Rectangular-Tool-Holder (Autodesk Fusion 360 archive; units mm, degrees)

design "Rectangular-Tool-Holder" references "Base"
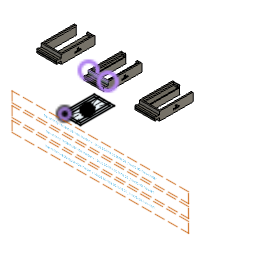
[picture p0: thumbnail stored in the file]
parameter "tool_width" = 36.5
parameter "tool_length" = 69
parameter "tool_slot_height" = 5
parameter "holder_hole_width" = 25
parameter "wall_thickness" = 5
sketch "Base" plane through (0, 0, 0) normal (0, 0, 1) x axis (1, 0, 0)
  line L1 (36.5, 0) -> (0, 0)
  line L2 (36.5, 69) -> (36.5, 0)
  line L3 (0, 69) -> (36.5, 69)
  line L4 (0, 0) -> (0, 69)
  line L5 (41.5, -5) -> (-5, -5)
  line L6 (41.5, 74) -> (41.5, -5)
  line L7 (-5, 74) -> (41.5, 74)
  line L8 (-5, -5) -> (-5, 74)
  line L9 (18.25, -5) -> (18.25, 74)
  line L10 (5.75, 74) -> (30.75, 74)
  line L11 (5.75, -5) -> (5.75, 74)
  line L12 (30.75, -5) -> (5.75, -5)
  line L13 (30.75, 74) -> (30.75, -5)
  line L14 (5.75, -5) -> (30.75, 74)
  line L15 (30.75, -5) -> (5.75, 74)
  point P1 (0, 0)
  point P2 (0, 0)
  point P10 (18.25, 74)
  point P11 (18.25, -5)
  point P16 (18.25, 34.5)
  point P3 (36.5, 0)
  point P5 (0, 69)
  point P14 (5.75, -5)
  point P15 (30.75, -5)
  point P13 (5.75, 74)
  horizontal L1
  vertical L2
  horizontal L3
  vertical L4
  coincident P1 P2
  midpoint L7 P10
  midpoint L5 P11
  horizontal L10
  perpendicular L10 L11
  parallel L10 L12
  parallel L11 L13
  coincident L14 P16
  coincident L15 P16
  midpoint L9 P16
  dimension "d7" distance P2 P3 = 36.5 (= "tool_width")
  dimension "d8" distance P2 P5 = 69 (= "tool_length")
  dimension "d9" = 5 (= "wall_thickness")
  dimension "d10" distance P14 P15 = 25 (= "holder_hole_width")
  dimension "d11" distance P13 P14 = 79 (= "tool_length + wall_thickness + wall_thickness")
extrude "Extrude1" new body sketch "Base" profile of L1 L2 L3 L4 L8 L7 L6 L5 L11 L13 against normal blind 5 (magnitude of "wall_thickness * -1")
extrude "Extrude2" add sketch "Base" profile of L1 L2 L3 L4 L8 L7 L6 L5 L11 L13 along normal blind 5 (= "tool_slot_height")
component_insert "Component Insert"
sketch "Reference" plane through (0, 55.6118, 0) normal (0, 1, 0) x axis (-1, 0, 0)
  line L1 (0, 52.6059) -> (-45, 52.6059)
  line L2 (0, 60) -> (0, 52.6059)
  line L3 (-45, 60) -> (0, 60)
  line L4 (-45, 52.6059) -> (-45, 60)
  line L5 (-45, 60) -> (0, 60)
move "Move1"
move "Move2"
extrude "Extrude3" new body of existing geometry blind 10
extrude "Extrude4" add of existing geometry to an object
extrude "Extrude5" cut of existing geometry to an object
extrude "Extrude6" add of existing geometry blind 10
sketch "Text 1" plane through (45.75, 0, 0) normal (1, 0, 0) x axis (0, 1, 0)
  line L1 (48.9918, 52.4859) -> (55.6118, 52.4859)
  line L2 (48.9918, 53.9359) -> (48.9918, 52.4859)
  line L3 (44.7318, 53.9359) -> (48.9918, 53.9359)
  line L4 (44.7318, 50.6559) -> (44.7318, 53.9359)
  line L5 (44.7318, 45.6759) -> (44.7318, 48.9559)
  line L6 (48.9918, 45.6759) -> (44.7318, 45.6759)
  line L7 (48.9918, 47.1259) -> (48.9918, 45.6759)
  line L8 (55.6118, 47.1259) -> (48.9918, 47.1259)
  curve K1
  curve K2
  curve K3
  curve K4
  line L9 (134.6118, 60) -> (55.6118, 60)
  line L10 (134.6118, 60) -> (134.6118, 40)
  line L11 (134.6118, 60) -> (134.6118, 40)
  line L12 (55.6118, 60) -> (134.6118, 60)
  line L13 (134.6118, 40) -> (55.6118, 40)
  line L14 (55.6118, 52.4859) -> (55.6118, 60)
  line L15 (55.6118, 40) -> (55.6118, 47.1259)
  arc A1 centre (44.7318, 49.8059) radius 0.85 clockwise from (44.7318, 50.6559) to (44.7318, 48.9559)
  parallel K3 L9
  equal K3 L9
  equal K2 L10
  midpoint L10
  dimension "d26" Text1-Height = 3
sketch "Text 2" plane through (-0.75, 0, 0) normal (-1, 0, 0) x axis (0, -1, 0)
  curve K1
  curve K2
  curve K3
  curve K4
  line L1 (-134.6118, 60) -> (-55.6118, 60)
  line L2 (-55.6118, 40) -> (-134.6118, 40)
  line L3 (-134.6118, 40) -> (-134.6118, 60)
  line L4 (-48.9918, 47.1259) -> (-55.6118, 47.1259)
  line L5 (-48.9918, 45.6759) -> (-48.9918, 47.1259)
  line L6 (-44.7318, 45.6759) -> (-48.9918, 45.6759)
  line L7 (-44.7318, 48.9559) -> (-44.7318, 45.6759)
  line L8 (-44.7318, 53.9359) -> (-44.7318, 50.6559)
  line L9 (-48.9918, 53.9359) -> (-44.7318, 53.9359)
  line L10 (-48.9918, 52.4859) -> (-48.9918, 53.9359)
  line L11 (-55.6118, 52.4859) -> (-48.9918, 52.4859)
  line L12 (-55.6118, 60) -> (-55.6118, 52.4859)
  line L13 (-55.6118, 47.1259) -> (-55.6118, 40)
  arc A1 centre (-44.7318, 49.8059) radius 0.85 clockwise from (-44.7318, 48.9559) to (-44.7318, 50.6559)
  point P3 (-134.6118, 60)
  point P2 (-55.6118, 40)
  equal K3 L1
  parallel K3 L1
  coincident P3
  coincident P2
  dimension "d27" Text1-Height = 3
extrude "Extrude7" cut sketch "Text 2" + "Text 1" distance -2
sketch "Filename" plane through (0, 0, 0) normal (0, 1, 0) x axis (1, 0, 0)
  dimension "d30" = 5
  dimension "d50" = 5
  dimension "d51" = 5
extrude "Extrude8" add of existing geometry to an object
extrude "Extrude9" cut of existing geometry to an object
copy_paste_bodies "CopyPasteBodies1"
move "Move3"
extrude "Extrude10" cut of existing geometry to an object
copy_paste_bodies "CopyPasteBodies2"
move "Move4"
extrude "Extrude11" cut of existing geometry to an object
extrude "Extrude12" cut of existing geometry to an object
extrude "Extrude13" add of existing geometry blind 5.5 (= "( ( 29 - 18 ) / 2 ) * 1 mm")
extrude "Extrude14" cut of existing geometry to an object
extrude "Extrude15" add of existing geometry blind 5.5 (= "( ( 29 - 18 ) / 2 ) * 1 mm")
fillet "Fillet1" radius 2
fillet "Fillet2" radius 1
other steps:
base_feature "Base Feature1" bodies "Right"
base_feature "Base Feature2" bodies "Center", "Left"
named bodies: "Center", "Right", "Left"

design "Base"
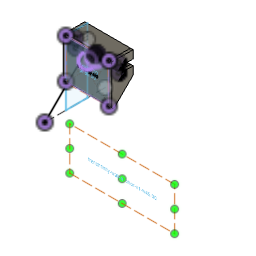
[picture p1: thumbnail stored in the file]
parameter "wall_anchor_height" = 60
parameter "wall_anchor_width" = 20
parameter "wall_anchor_angle" = 45
parameter "width_per_slot" = 40
parameter "slot_inner_width" = 8.5
parameter "slot_inner_height" = 4.5
parameter "slot_outer_width" = 5.6
parameter "slot_outer_height" = 6.5
parameter "slot_dept" = 15
parameter "print_tolerance" = 0.12
parameter "base_plate_thickness" = 16
parameter "base_plate_slot_height" = 50
parameter "wall_anchor_angle_rounded_border" = 1.5
parameter "base_plate_screw_hole_diameter" = 4
parameter "base_plate_screw_head_diameter" = 8
parameter "base_plate_screw_head_height" = 4
parameter "base_plate_screw_hole_side_distance" = 7
parameter "slot_screw_head_width" = 4.42 (= "4.3 mm + print_tolerance")
parameter "slot_screw_thread_width" = 2.12 (= "2 mm + print_tolerance")
parameter "slot_screw_head_height" = 2.12 (= "2 mm + print_tolerance")
parameter "width" = 45
parameter "filament_hole_width" = 1.7
parameter "plate_height" = 80
sketch "Side" plane through (0, 0, 0) normal (1, 0, 0) x axis (0, 1, 0)
  line L1 (39.6118, 0) -> (19.6118, 0)
  line L2 (39.6118, 60) -> (39.6118, 0)
  line L3 (19.6118, 60) -> (39.6118, 60)
  line L4 (19.6118, 0) -> (19.6118, 60)
  line L5 (39.6118, 39.6118) -> (0, 0)
  line L6 (56.0196, 0) -> (0, 0)
  point P1 (0, 0)
  point P6 (0, 0)
  point P7 (39.6118, 39.6118)
  point P2 (19.6118, 0)
  point P3 (39.6118, 0)
  point P5 (19.6118, 60)
  horizontal L1
  vertical L2
  horizontal L3
  vertical L4
  horizontal L6
  coincident P1 P6
  coincident L2 P7
  dimension "d4" distance P2 P3 = 20 (= "wall_anchor_width")
  dimension "d5" distance P2 P5 = 60 (= "wall_anchor_height")
  dimension "d6" angle L5 L6 = 45 (= "wall_anchor_angle")
extrude "Extrude1" new body sketch "Side" profile of L1 L2 L3 L4 L5 along normal blind 40 (= "width_per_slot")
sketch "Slot LeftToRight" plane through (0, 0, 0) normal (-1, 0, 0) x axis (0, -1, 0)
  line L1 (-19.6118, 60) -> (-19.6118, 19.6118)
  line L2 (-39.6118, 60) -> (-19.6118, 60)
  line L3 (-39.6118, 39.6118) -> (-39.6118, 60)
  line L4 (-19.6118, 19.6118) -> (-39.6118, 39.6118)
  line L5 (-39.6118, 52.6059) -> (-39.6118, 49.8059)
  line L6 (-39.6118, 47.0059) -> (-39.6118, 49.8059)
  line L7 (-33.1118, 52.6059) -> (-39.6118, 52.6059)
  line L8 (-28.6118, 49.8059) -> (-39.6118, 49.8059)
  line L9 (-28.6118, 54.0559) -> (-28.6118, 49.8059)
  line L10 (-33.1118, 54.0559) -> (-28.6118, 54.0559)
  line L11 (-33.1118, 52.6059) -> (-33.1118, 54.0559)
  line L12 (-28.6118, 45.5559) -> (-28.6118, 49.8059)
  line L13 (-33.1118, 45.5559) -> (-28.6118, 45.5559)
  line L14 (-33.1118, 47.0059) -> (-33.1118, 45.5559)
  line L15 (-33.1118, 47.0059) -> (-39.6118, 47.0059)
  point P6 (-39.6118, 49.8059)
  point P7 (-39.6118, 52.6059)
  point P17 (-39.6118, 47.0059)
  point P9 (-33.1118, 52.6059)
  point P16 (-33.1118, 47.0059)
  point P10 (-28.6118, 49.8059)
  point P13 (-28.6118, 49.8059)
  point P11 (-28.6118, 54.0559)
  point P14 (-28.6118, 45.5559)
  point P12 (-33.1118, 54.0559)
  point P15 (-33.1118, 45.5559)
  midpoint L3 P6
  parallel L3 L5
  parallel L3 L6
  perpendicular L3 L7
  perpendicular L6 L8
  perpendicular L8 L9
  perpendicular L9 L10
  symmetric P7 L8 P17
  symmetric P9 L8 P16
  symmetric P10 L8 P13
  symmetric L8 P11 P14
  symmetric L8 P12 P15
  dimension "d80" distance P6 P7 = 2.8 (= "slot_outer_width / 2")
  dimension "d82" distance P7 P9 = 6.5 (= "slot_outer_height")
  dimension "d84" distance P6 P10 = 11 (= "slot_outer_height + slot_inner_height")
  dimension "d85" distance P10 P11 = 4.25 (= "slot_inner_width / 2")
  dimension "d86" distance P11 P12 = 4.5 (= "slot_inner_height")
extrude "Extrude3" cut sketch "Slot LeftToRight" profile of L3 L5 L6 L7 L9 L10 L11 L12 L13 L14 L15 against normal blind 40 (magnitude of "width_per_slot * -1")
sketch "Plate" plane through (0, 39.6118, 0) normal (0, 1, 0) x axis (-1, 0, 0)
  line L1 (0, 39.6118) -> (-40, 39.6118)
  line L2 (-40, 60) -> (0, 60)
  line L3 (0, 10) -> (0, 60)
  line L4 (-40, 10) -> (-40, 60)
  line L5 (-40, 10) -> (0, 10)
  line L6 (-40, 47.0059) -> (0, 47.0059)
  line L7 (-40, 52.6059) -> (-40, 60)
  line L8 (0, 60) -> (0, 52.6059)
  line L9 (0, 52.6059) -> (-40, 52.6059)
  line L10 (-40, 60) -> (0, 60)
  line L11 (-40, 39.6118) -> (-40, 47.0059)
  line L12 (0, 47.0059) -> (0, 39.6118)
  point P2 (0, 60)
  point P3 (-40, 60)
  point P4 (0, 10)
  point P5 (-40, 10)
  perpendicular L1 L3
  perpendicular L1 L4
  dimension "d36" distance P2 P3 = 40 (= "width_per_slot")
  dimension "d37" distance P2 P4 = 50 (= "base_plate_slot_height")
  dimension "d39" distance P3 P5 = 50 (= "base_plate_slot_height")
extrude "Extrude6" new body sketch "Plate" profile of L1 L2 L3 L4 L5 L6 L7 L8 L9 L10 along normal blind 16 (= "base_plate_thickness") bodies "Base plate with slot"
sketch "Slot" plane through (0, 0, 0) normal (-1, 0, 0) x axis (0, -1, 0)
  line L1 (-19.6118, 60) -> (-19.6118, 19.6118)
  line L2 (-39.6118, 60) -> (-19.6118, 60)
  line L3 (-39.6118, 52.6059) -> (-39.6118, 60)
  line L4 (-33.1118, 52.6059) -> (-39.6118, 52.6059)
  line L5 (-33.1118, 54.0559) -> (-33.1118, 52.6059)
  line L6 (-28.6118, 54.0559) -> (-33.1118, 54.0559)
  line L7 (-28.6118, 45.5559) -> (-28.6118, 54.0559)
  line L8 (-33.1118, 45.5559) -> (-28.6118, 45.5559)
  line L9 (-33.1118, 47.0059) -> (-33.1118, 45.5559)
  line L10 (-39.6118, 47.0059) -> (-33.1118, 47.0059)
  line L11 (-39.6118, 39.6118) -> (-39.6118, 47.0059)
  line L12 (-19.6118, 19.6118) -> (-39.6118, 39.6118)
  line L13 (-33.1118, 52.6059) -> (-39.6118, 52.6059)
  line L14 (-33.1118, 54.0559) -> (-33.1118, 52.6059)
  line L15 (-28.6118, 54.0559) -> (-33.1118, 54.0559)
  line L16 (-28.6118, 45.5559) -> (-28.6118, 54.0559)
  line L17 (-33.1118, 45.5559) -> (-28.6118, 45.5559)
  line L18 (-33.1118, 47.0059) -> (-33.1118, 45.5559)
  line L19 (-39.6118, 47.0059) -> (-33.1118, 47.0059)
  line L20 (-39.6118, 10) -> (-39.6118, 60)
  line L21 (-32.9918, 52.4859) -> (-39.6118, 52.4859)
  line L22 (-32.9918, 53.9359) -> (-32.9918, 52.4859)
  line L23 (-28.7318, 53.9359) -> (-32.9918, 53.9359)
  line L24 (-28.7318, 45.6759) -> (-28.7318, 53.9359)
  line L25 (-32.9918, 45.6759) -> (-28.7318, 45.6759)
  line L26 (-32.9918, 47.1259) -> (-32.9918, 45.6759)
  line L27 (-39.6118, 47.1259) -> (-32.9918, 47.1259)
  line L28 (-33.1118, 52.6059) -> (-39.6118, 52.6059)
  line L29 (-33.1118, 52.6059) -> (-33.1118, 54.0559)
  line L30 (-28.6118, 54.0559) -> (-33.1118, 54.0559)
  line L31 (-28.6118, 45.5559) -> (-28.6118, 54.0559)
  line L32 (-33.1118, 45.5559) -> (-28.6118, 45.5559)
  line L33 (-33.1118, 47.0059) -> (-33.1118, 45.5559)
  line L34 (-39.6118, 47.0059) -> (-33.1118, 47.0059)
  line L35 (-39.6118, 47.0059) -> (-39.6118, 52.6059)
  line L36 (-49.1118, 52.6059) -> (-55.6118, 52.6059)
  line L37 (-49.1118, 52.6059) -> (-49.1118, 54.0559)
  line L38 (-44.6118, 54.0559) -> (-49.1118, 54.0559)
  line L39 (-44.6118, 45.5559) -> (-44.6118, 54.0559)
  line L40 (-49.1118, 45.5559) -> (-44.6118, 45.5559)
  line L41 (-49.1118, 47.0059) -> (-49.1118, 45.5559)
  line L42 (-55.6118, 47.0059) -> (-49.1118, 47.0059)
  line L43 (-55.6118, 47.0059) -> (-55.6118, 52.6059)
  point P15 (-39.6118, 52.6059)
  point P33 (-39.6118, 52.6059)
  point P16 (-33.1118, 52.6059)
  point P34 (-33.1118, 52.6059)
  point P17 (-33.1118, 54.0559)
  point P35 (-33.1118, 54.0559)
  point P36 (-33.1118, 52.6059)
  point P18 (-28.6118, 54.0559)
  point P37 (-28.6118, 54.0559)
  point P19 (-28.6118, 45.5559)
  point P38 (-28.6118, 45.5559)
  point P10 (-28.6118, 45.5559)
  point P39 (-28.6118, 45.5559)
  point P11 (-33.1118, 45.5559)
  point P40 (-33.1118, 45.5559)
  point P41 (-33.1118, 45.5559)
  point P12 (-33.1118, 47.0059)
  point P42 (-33.1118, 47.0059)
  point P21 (-33.1118, 47.0059)
  point P43 (-33.1118, 47.0059)
  point P22 (-39.6118, 47.0059)
  point P44 (-39.6118, 47.0059)
  point P45 (-39.6118, 52.6059)
  point P46 (-39.6118, 47.0059)
  coincident P15 P33
  coincident P16 P34
  coincident P17 P35
  coincident P16 P36
  coincident P18 P37
  coincident P19 P38
  coincident P10 P39
  coincident P11 P40
  coincident P11 P41
  coincident P12 P42
  coincident P21 P43
  coincident P22 P44
  coincident P15 P45
  coincident P22 P46
  dimension "d91" = 0.12 (= "print_tolerance")
  dimension "d96" R-Pattern1-uDistance = -16 (= "base_plate_thickness * -1")
  dimension "d97" R-Pattern1-vDistance = 0
extrude "Extrude7" add sketch "Slot" profile of L20 L24 L23 L27 L22 L25 L26 L21 against normal blind 40 (magnitude of "width_per_slot * -1")
extrude "Extrude8" cut sketch "Slot" profile of L36 L37 L38 L39 L40 L41 L42 L43 no distance stored
sketch "Sketch3" plane through (0, 0, 0) normal (-1, 0, 0) x axis (0, -1, 0)
  line L1 (-32.9918, 47.1259) -> (-39.6118, 47.1259)
  line L2 (-32.9918, 45.6759) -> (-32.9918, 47.1259)
  line L3 (-28.7318, 45.6759) -> (-32.9918, 45.6759)
  line L4 (-28.7318, 53.9359) -> (-28.7318, 45.6759)
  line L5 (-32.9918, 53.9359) -> (-28.7318, 53.9359)
  line L6 (-32.9918, 52.4859) -> (-32.9918, 53.9359)
  line L7 (-39.6118, 52.4859) -> (-32.9918, 52.4859)
  line L8 (-44.6118, 45.5559) -> (-44.6118, 54.0559)
  line L9 (-32.9918, 52.4859) -> (-39.6118, 52.4859)
  line L10 (-32.9918, 53.9359) -> (-32.9918, 52.4859)
  line L11 (-28.7318, 53.9359) -> (-32.9918, 53.9359)
  line L12 (-28.7318, 45.6759) -> (-28.7318, 53.9359)
  line L13 (-32.9918, 45.6759) -> (-28.7318, 45.6759)
  line L14 (-32.9918, 47.1259) -> (-32.9918, 45.6759)
  line L15 (-39.6118, 47.1259) -> (-32.9918, 47.1259)
  line L16 (-39.6118, 47.1259) -> (-39.6118, 52.4859)
  line L17 (-55.6118, 52.4859) -> (-48.9918, 52.4859)
  line L18 (-48.9918, 52.4859) -> (-48.9918, 53.9359)
  line L19 (-48.9918, 53.9359) -> (-44.7318, 53.9359)
  line L20 (-44.7318, 45.6759) -> (-44.7318, 53.9359)
  line L21 (-48.9918, 45.6759) -> (-44.7318, 45.6759)
  line L22 (-48.9918, 47.1259) -> (-48.9918, 45.6759)
  line L23 (-55.6118, 47.1259) -> (-48.9918, 47.1259)
  line L24 (-55.6118, 47.1259) -> (-55.6118, 52.4859)
  line L25 (-55.6118, 47.0059) -> (-49.1118, 47.0059)
  line L26 (-55.6118, 10) -> (-55.6118, 47.0059)
  line L27 (-39.6118, 10) -> (-55.6118, 10)
  line L28 (-39.6118, 47.1259) -> (-39.6118, 10)
  line L29 (-39.6118, 60) -> (-39.6118, 52.4859)
  line L30 (-55.6118, 60) -> (-39.6118, 60)
  line L31 (-55.6118, 52.6059) -> (-55.6118, 60)
  line L32 (-49.1118, 52.6059) -> (-55.6118, 52.6059)
  line L33 (-49.1118, 54.0559) -> (-49.1118, 52.6059)
  line L34 (-44.6118, 54.0559) -> (-49.1118, 54.0559)
  line L35 (-49.1118, 45.5559) -> (-44.6118, 45.5559)
  line L36 (-49.1118, 47.0059) -> (-49.1118, 45.5559)
  point P9 (-39.6118, 52.4859)
  point P20 (-39.6118, 52.4859)
  point P19 (-39.6118, 47.1259)
  point P21 (-39.6118, 47.1259)
  coincident P9 P20
  coincident P19 P21
  dimension "d105" R-Pattern1-vDistance = 0
extrude "Extrude3" new body sketch "Sketch3" profile of L17 L18 L19 L20 L21 L22 L23 L24 against normal blind 40 (magnitude of "width_per_slot * -1")
sketch "Screw hole" plane through (0, 28.6118, 0) normal (0, 1, 0) x axis (-1, 0, 0)
  line L1 (0, 54.0559) -> (0, 45.5559)
  line L2 (-40, 54.0559) -> (0, 54.0559)
  line L3 (-40, 45.5559) -> (-40, 54.0559)
  line L4 (0, 45.5559) -> (-40, 45.5559)
  line L5 (0, 45.5559) -> (-40, 54.0559)
  line L6 (-40, 45.5559) -> (0, 54.0559)
  circle C1 centre (-20, 49.8059) radius 2.21
  circle C2 centre (-20, 49.8059) radius 1.06
  point P4 (-40, 54.0559)
  point P6 (-40, 54.0559)
  point P2 (0, 45.5559)
  point P7 (0, 45.5559)
  point P3 (0, 54.0559)
  point P8 (0, 54.0559)
  point P5 (-40, 45.5559)
  point P9 (-40, 45.5559)
  point P10 (-20, 49.8059)
  coincident P4 P6
  coincident P2 P7
  coincident P3 P8
  coincident P5 P9
  midpoint L5 P10
  concentric C1 C2
  dimension "d119" diameter C1 = 4.42 (= "slot_screw_head_width")
  dimension "d120" diameter C2 = 2.12 (= "slot_screw_thread_width")
extrude "Extrude4" cut sketch "Screw hole" profile of C2 against normal blind 2000
extrude "Extrude5" cut sketch "Screw hole" profile of C1 C2 no distance stored
fillet "Fillet1" radius 1.5 (= "wall_anchor_angle_rounded_border")
work_plane "WorkPlane1" sketch "Slot LeftToRight" AlongDistance -20 (= "-width_per_slot / 2")
sketch "Screw head" plane through (20, 0, 0) normal (-1, 0, 0) x axis (0, -1, 0)
  line L1 (-28.6118, 52.0159) -> (-28.6118, 47.5959)
  line L2 (-26.4918, 52.0159) -> (-26.4918, 47.5959)
  line L3 (-26.4918, 48.7459) -> (-26.4918, 50.8659)
  line L4 (-26.4918, 50.8659) -> (-28.6118, 52.0159)
  line L5 (-26.4918, 52.0159) -> (-28.6118, 52.0159)
  point P3 (-28.6118, 52.0159)
  point P8 (-28.6118, 52.0159)
  point P6 (-26.4918, 50.8659)
  point P9 (-26.4918, 50.8659)
  point P10 (-28.6118, 52.0159)
  point P5 (-26.4918, 52.0159)
  point P11 (-26.4918, 52.0159)
  coincident P3 P8
  coincident P6 P9
  coincident P3 P10
  coincident P5 P11
revolve "Revolve1" sketch "Screw head" AlongAngle 360
sketch "Plate" plane through (0, 39.6118, 0) normal (0, 1, 0) x axis (-1, 0, 0)
  line L1 (0, 39.6118) -> (-40, 39.6118)
  line L2 (-40, 60) -> (0, 60)
  line L3 (0, 10) -> (0, 60)
  line L4 (-40, 10) -> (-40, 60)
  line L5 (-40, 10) -> (0, 10)
  line L6 (-40, 47.0059) -> (0, 47.0059)
  line L7 (-40, 39.6118) -> (-40, 47.0059)
  line L8 (0, 47.0059) -> (0, 39.6118)
  line L9 (0, 52.6059) -> (-40, 52.6059)
  line L10 (-40, 60) -> (0, 60)
  line L11 (0, 60) -> (0, 52.6059)
  line L12 (-40, 52.6059) -> (-40, 60)
  point P2 (0, 60)
  point P3 (-40, 60)
  point P4 (0, 10)
  point P5 (-40, 10)
  perpendicular L1 L3
  perpendicular L1 L4
  dimension "d36_1" distance P2 P3 = 40 (= "width_per_slot")
  dimension "d37_1" distance P2 P4 = 50 (= "base_plate_slot_height")
  dimension "d39_1" distance P3 P5 = 50 (= "base_plate_slot_height")
extrude "Extrude6" new body sketch "Plate" profile of L1 L2 L3 L4 L5 L6 L7 L8 L9 L10 along normal blind 16 (= "base_plate_thickness") named "d89_1" bodies "Base plate with slot"
sketch "Slot" plane through (0, 0, 0) normal (-1, 0, 0) x axis (0, -1, 0)
  line L1 (-19.6118, 60) -> (-19.6118, 23.2332)
  line L2 (-39.6118, 60) -> (-19.6118, 60)
  line L3 (-39.6118, 52.6059) -> (-39.6118, 60)
  line L4 (-33.1118, 52.6059) -> (-39.6118, 52.6059)
  line L5 (-33.1118, 54.0559) -> (-33.1118, 52.6059)
  line L6 (-28.6118, 54.0559) -> (-33.1118, 54.0559)
  line L7 (-28.6118, 45.5559) -> (-28.6118, 54.0559)
  line L8 (-33.1118, 45.5559) -> (-28.6118, 45.5559)
  line L9 (-33.1118, 47.0059) -> (-33.1118, 45.5559)
  line L10 (-39.6118, 47.0059) -> (-33.1118, 47.0059)
  line L11 (-39.6118, 39.6118) -> (-39.6118, 47.0059)
  line L12 (-22.1725, 22.1725) -> (-39.6118, 39.6118)
  line L13 (-33.1118, 52.6059) -> (-39.6118, 52.6059)
  line L14 (-33.1118, 54.0559) -> (-33.1118, 52.6059)
  line L15 (-28.6118, 54.0559) -> (-33.1118, 54.0559)
  line L16 (-28.6118, 45.5559) -> (-28.6118, 54.0559)
  line L17 (-33.1118, 45.5559) -> (-28.6118, 45.5559)
  line L18 (-33.1118, 47.0059) -> (-33.1118, 45.5559)
  line L19 (-39.6118, 47.0059) -> (-33.1118, 47.0059)
  line L20 (-39.6118, 10) -> (-39.6118, 60)
  line L21 (-32.9918, 52.4859) -> (-39.6118, 52.4859)
  line L22 (-32.9918, 53.9359) -> (-32.9918, 52.4859)
  line L23 (-28.7318, 53.9359) -> (-32.9918, 53.9359)
  line L24 (-28.7318, 45.6759) -> (-28.7318, 53.9359)
  line L25 (-32.9918, 45.6759) -> (-28.7318, 45.6759)
  line L26 (-32.9918, 47.1259) -> (-32.9918, 45.6759)
  line L27 (-39.6118, 47.1259) -> (-32.9918, 47.1259)
  line L28 (-33.1118, 52.6059) -> (-39.6118, 52.6059)
  line L29 (-33.1118, 52.6059) -> (-33.1118, 54.0559)
  line L30 (-28.6118, 54.0559) -> (-33.1118, 54.0559)
  line L31 (-28.6118, 45.5559) -> (-28.6118, 54.0559)
  line L32 (-33.1118, 45.5559) -> (-28.6118, 45.5559)
  line L33 (-33.1118, 47.0059) -> (-33.1118, 45.5559)
  line L34 (-39.6118, 47.0059) -> (-33.1118, 47.0059)
  line L35 (-39.6118, 47.0059) -> (-39.6118, 52.6059)
  line L36 (-49.1118, 52.6059) -> (-55.6118, 52.6059)
  line L37 (-49.1118, 52.6059) -> (-49.1118, 54.0559)
  line L38 (-44.6118, 54.0559) -> (-49.1118, 54.0559)
  line L39 (-44.6118, 45.5559) -> (-44.6118, 54.0559)
  line L40 (-49.1118, 45.5559) -> (-44.6118, 45.5559)
  line L41 (-49.1118, 47.0059) -> (-49.1118, 45.5559)
  line L42 (-55.6118, 47.0059) -> (-49.1118, 47.0059)
  line L43 (-55.6118, 47.0059) -> (-55.6118, 52.6059)
  arc A1 centre (-21.1118, 23.2332) radius 1.5 clockwise from (-19.6118, 23.2332) to (-22.1725, 22.1725)
  point P15 (-39.6118, 52.6059)
  point P33 (-39.6118, 52.6059)
  point P16 (-33.1118, 52.6059)
  point P34 (-33.1118, 52.6059)
  point P17 (-33.1118, 54.0559)
  point P35 (-33.1118, 54.0559)
  point P36 (-33.1118, 52.6059)
  point P18 (-28.6118, 54.0559)
  point P37 (-28.6118, 54.0559)
  point P19 (-28.6118, 45.5559)
  point P38 (-28.6118, 45.5559)
  point P10 (-28.6118, 45.5559)
  point P39 (-28.6118, 45.5559)
  point P11 (-33.1118, 45.5559)
  point P40 (-33.1118, 45.5559)
  point P41 (-33.1118, 45.5559)
  point P12 (-33.1118, 47.0059)
  point P42 (-33.1118, 47.0059)
  point P21 (-33.1118, 47.0059)
  point P43 (-33.1118, 47.0059)
  point P22 (-39.6118, 47.0059)
  point P44 (-39.6118, 47.0059)
  point P45 (-39.6118, 52.6059)
  point P46 (-39.6118, 47.0059)
  coincident P15 P33
  coincident P16 P34
  coincident P17 P35
  coincident P16 P36
  coincident P18 P37
  coincident P19 P38
  coincident P10 P39
  coincident P11 P40
  coincident P11 P41
  coincident P12 P42
  coincident P21 P43
  coincident P22 P44
  coincident P15 P45
  coincident P22 P46
  dimension "d91_1" = 0.12 (= "print_tolerance")
  dimension "d96_1" R-Pattern1-uDistance = -16 (= "base_plate_thickness * -1")
  dimension "d97_1" R-Pattern1-vDistance = 0
extrude "Extrude8" cut sketch "Slot" profile of L36 L37 L38 L39 L40 L41 L42 L43 no distance stored
sketch "Screw" plane through (0, 55.6118, 0) normal (0, 1, 0) x axis (-1, 0, 0)
  line L1 (-40, 47.0059) -> (0, 47.0059)
  line L2 (-40, 10) -> (-40, 47.0059)
  line L3 (0, 10) -> (-40, 10)
  line L4 (0, 47.0059) -> (0, 10)
  line L5 (-33, 17) -> (-33, 40.0059)
  line L6 (-7, 17) -> (-33, 17)
  line L7 (-7, 40.0059) -> (-7, 17)
  line L8 (-33, 40.0059) -> (-7, 40.0059)
  circle C1 centre (-33, 17) radius 4
  circle C2 centre (-33, 17) radius 2
  point P7 (-33, 17)
  point P10 (-33, 17)
  coincident P7 P10
  concentric C1 C2
  dimension "d127" = -7 (= "base_plate_screw_hole_side_distance * -1")
  dimension "d128" diameter C1 = 8
  dimension "d129" diameter C2 = 4
rectangular_pattern "R-Pattern2" countU 1 (= "floor(( width / mm ) / ( width_per_slot / cm * 10 ))") uSpaceDistance 40 (= "width_per_slot") vSpaceDistance 0
work_plane "WorkPlane2"
extrude "Extrude12" new body of existing geometry no distance stored
mirror "Mirror3" mirrorStitchTolerance 0.1
sketch "filename" plane through (0, 19.6118, 0) normal (0, -1, 0) x axis (1, 0, 0)
  dimension "d216" = 3
sketch "Text" plane through (0, 19.6118, 0) normal (0, -1, 0) x axis (1, 0, 0)
  line L1 (42.5, 60) -> (42.5, 23.2332)
  line L2 (40, 23.2332) -> (40, 60)
  line L3 (42.5, 23.2332) -> (40, 23.2332)
  line L4 (42.5, 60) -> (42.5, 23.2332)
  line L5 (40, 60) -> (42.5, 60)
  line L6 (0, 60) -> (0, 23.2332)
  line L7 (-2.5, 60) -> (0, 60)
  line L8 (-2.5, 23.2332) -> (-2.5, 60)
  line L9 (0, 23.2332) -> (-2.5, 23.2332)
  curve K1
  curve K2
  curve K3
  curve K4
  line L10 (80, 60) -> (40, 60)
  point P4 (42.5, 23.2332)
  point P2 (-2.5, 60)
  coincident P4
  coincident P2
  parallel K3 L10
  dimension "d229" Text1-Height = 3
extrude "Extrude19" cut sketch "Text" against normal blind 2
extrude "Extrude14" cut of existing geometry blind 2.5 (= "( width_per_slot - width ) / -2")
extrude "Extrude15" cut of existing geometry blind 2.5 (= "( width_per_slot - width ) / -2")
extrude "Extrude9" cut of existing geometry blind -39 (= "-width_per_slot + 1 mm")
extrude "Extrude10" add of existing geometry blind 44 (= "width - 1 mm")
extrude "Extrude13" cut of existing geometry blind -30
extrude "Extrude14" add of existing geometry blind 80 (= "plate_height")
sketch "Sketch7" plane through (0, 39.6118, 0) normal (0, -1, 0) x axis (1, 0, 0)
  dimension "d236" = 3
extrude "Extrude11" cut sketch "Sketch7" against normal blind 2
sketch "File name" plane through (0, 39.6118, 0) normal (0, -1, 0) x axis (1, 0, 0)
  line L1 (16.5624, 7.4163) -> (16.325, 7.4163)
  line L2 (16.5624, 4.404) -> (16.5624, 7.4163)
  line L3 (16.1941, 4.404) -> (16.5624, 4.404)
  line L4 (16.1941, 6.7512) -> (16.1941, 4.404)
  curve K1 (15.8441, 6.4975) -> (16.1941, 6.7512)
  curve K2 (15.4574, 6.3072) -> (15.8441, 6.4975)
  line L5 (15.4574, 6.6632) -> (15.4574, 6.3072)
  curve K3 (15.9976, 7.0152) -> (15.4574, 6.6632)
  curve K4 (16.325, 7.4163) -> (15.9976, 7.0152)
  line L6 (19.7896, 4.404) -> (20.2295, 6.0759)
  line L7 (19.4048, 4.404) -> (19.7896, 4.404)
  line L8 (18.7398, 6.5773) -> (19.4048, 4.404)
  line L9 (19.1204, 6.5773) -> (18.7398, 6.5773)
  line L10 (19.4662, 5.3229) -> (19.1204, 6.5773)
  line L11 (19.5952, 4.8563) -> (19.4662, 5.3229)
  curve K5 (19.7077, 5.3044) -> (19.5952, 4.8563)
  line L12 (20.0535, 6.5773) -> (19.7077, 5.3044)
  line L13 (20.4321, 6.5773) -> (20.0535, 6.5773)
  line L14 (20.7575, 5.3167) -> (20.4321, 6.5773)
  line L15 (20.866, 4.9013) -> (20.7575, 5.3167)
  line L16 (20.9908, 5.3208) -> (20.866, 4.9013)
  line L17 (21.3632, 6.5773) -> (20.9908, 5.3208)
  line L18 (21.7214, 6.5773) -> (21.3632, 6.5773)
  line L19 (21.042, 4.404) -> (21.7214, 6.5773)
  line L20 (20.6593, 4.404) -> (21.042, 4.404)
  line L21 (20.3134, 5.7055) -> (20.6593, 4.404)
  line L22 (20.2295, 6.0759) -> (20.3134, 5.7055)
  line L23 (18.5965, 5.3044) -> (18.5965, 5.6748)
  line L24 (17.4649, 5.3044) -> (18.5965, 5.3044)
  line L25 (17.4649, 5.6748) -> (17.4649, 5.3044)
  line L26 (18.5965, 5.6748) -> (17.4649, 5.6748)
  line L27 (14.1293, 4.404) -> (14.9519, 6.5773)
  line L28 (13.7855, 4.404) -> (14.1293, 4.404)
  line L29 (12.9587, 6.5773) -> (13.7855, 4.404)
  line L30 (13.3475, 6.5773) -> (12.9587, 6.5773)
  line L31 (13.8141, 5.2758) -> (13.3475, 6.5773)
  curve K6 (13.9533, 4.8379) -> (13.8141, 5.2758)
  curve K7 (14.0904, 5.2512) -> (13.9533, 4.8379)
  line L32 (14.5733, 6.5773) -> (14.0904, 5.2512)
  line L33 (14.9519, 6.5773) -> (14.5733, 6.5773)
  line L34 (0, 47.1259) -> (45, 47.1259)
  line L35 (0, -40) -> (0, 47.1259)
  line L36 (45, 47.1259) -> (45, -40)
  curve K8
  curve K9
  curve K10
  curve K11
  line L37 (45, -40) -> (0, -40)
  curve K12 (24.8441, 4.7969) -> (24.6456, 5.2226)
  line L38 (23.1088, 5.1223) -> (23.1088, 4.404)
  curve K13 (25.2227, 4.6557) -> (24.8441, 4.7969)
  curve K14 (19.9778, 1.0786) -> (19.8305, 0.5896)
  curve K15 (27.8626, 6.7389) -> (27.7541, 5.8836)
  line L39 (23.8823, 5.1223) -> (23.8823, 5.46)
  line L40 (23.4771, 5.1223) -> (23.8823, 5.1223)
  line L41 (21.8073, 5.1223) -> (23.1088, 5.1223)
  line L42 (23.4771, 7.404) -> (23.1763, 7.404)
  curve K16 (25.6729, 4.8563) -> (25.2227, 4.6557)
  curve K17 (25.8571, 5.3883) -> (25.6729, 4.8563)
  curve K18 (25.6791, 5.8856) -> (25.8571, 5.3883)
  curve K19 (25.2166, 6.0677) -> (25.6791, 5.8856)
  curve K20 (30.5188, 7.2403) -> (30.1934, 6.7389)
  curve K21 (31.0631, 7.4163) -> (30.5188, 7.2403)
  curve K22 (31.4867, 7.3181) -> (31.0631, 7.4163)
  curve K23 (31.7875, 7.0377) -> (31.4867, 7.3181)
  curve K24 (28.4253, 2.5582) -> (28.0999, 2.0568)
  curve K25 (28.9696, 2.7342) -> (28.4253, 2.5582)
  curve K26 (29.3932, 2.6359) -> (28.9696, 2.7342)
  curve K27 (29.6941, 2.3556) -> (29.3932, 2.6359)
  curve K28 (25.7691, 2.0568) -> (25.6606, 1.2014)
  curve K29 (21.2425, 1.3488) -> (21.574, 1.5862)
  curve K30 (21.662, 1.0582) -> (21.2425, 1.3488)
  curve K31 (21.8073, 0.5793) -> (21.662, 1.0582)
  curve K32 (21.5351, -0.0673) -> (21.8073, 0.5793)
  curve K33 (20.4014, 1.3488) -> (19.9778, 1.0786)
  curve K34 (15.8789, 1.8604) -> (15.6108, 1.6128)
  curve K35 (16.2411, 1.9443) -> (15.8789, 1.8604)
  curve K36 (30.1934, 6.7389) -> (30.0849, 5.8836)
  line L43 (15.6436, -1.111) -> (15.6436, -0.053)
  line L44 (15.2752, -1.111) -> (15.6436, -1.111)
  curve K37 (19.8305, 0.5896) -> (20.1027, -0.0673)
  curve K38 (28.0999, 2.0568) -> (27.9915, 1.2014)
  line L45 (17.9744, -0.2781) -> (17.9744, 0.9108)
  curve K39 (20.0617, 1.5882) -> (20.4014, 1.3488)
  curve K40 (19.9512, 1.9606) -> (20.0617, 1.5882)
  curve K41 (20.1866, 2.5111) -> (19.9512, 1.9606)
  curve K42 (21.574, 1.5862) -> (21.6845, 1.9504)
  curve K43 (25.3148, 6.3931) -> (24.748, 6.2048)
  curve K44 (25.9778, 6.1209) -> (25.3148, 6.3931)
  curve K45 (26.248, 5.4211) -> (25.9778, 6.1209)
  curve K46 (26.0106, 4.7171) -> (26.248, 5.4211)
  curve K47 (25.2227, 4.3529) -> (26.0106, 4.7171)
  curve K48 (24.5535, 4.5821) -> (25.2227, 4.3529)
  curve K49 (24.2589, 5.1898) -> (24.5535, 4.5821)
  line L46 (23.4771, 4.404) -> (23.4771, 5.1223)
  line L47 (23.1088, 4.404) -> (23.4771, 4.404)
  line L48 (21.8073, 5.46) -> (21.8073, 5.1223)
  line L49 (23.1763, 7.404) -> (21.8073, 5.46)
  line L50 (23.4771, 5.46) -> (23.4771, 7.404)
  line L51 (23.8823, 5.46) -> (23.4771, 5.46)
  line L52 (27.2159, 4.404) -> (27.2159, 4.8235)
  line L53 (26.7964, 4.404) -> (27.2159, 4.404)
  line L54 (26.7964, 4.8235) -> (26.7964, 4.404)
  line L55 (27.2159, 4.8235) -> (26.7964, 4.8235)
  curve K50 (28.2882, -0.0182) -> (28.9696, -0.3293)
  curve K51 (27.9915, 1.2014) -> (28.2882, -0.0182)
  curve K52 (29.8803, 1.9095) -> (29.6941, 2.3556)
  curve K53 (29.9478, 1.2014) -> (29.8803, 1.9095)
  curve K54 (29.8394, 0.3481) -> (29.9478, 1.2014)
  curve K55 (29.514, -0.1533) -> (29.8394, 0.3481)
  curve K56 (28.9696, -0.3293) -> (29.514, -0.1533)
  line L56 (15.2752, 1.8952) -> (15.2752, -1.111)
  line L57 (15.6108, 1.8952) -> (15.2752, 1.8952)
  line L58 (15.6108, 1.6128) -> (15.6108, 1.8952)
  curve K57 (16.7323, 1.801) -> (16.2411, 1.9443)
  curve K58 (17.0535, 1.3958) -> (16.7323, 1.801)
  curve K59 (17.162, 0.8249) -> (17.0535, 1.3958)
  curve K60 (17.0413, 0.2233) -> (17.162, 0.8249)
  curve K61 (16.6934, -0.186) -> (17.0413, 0.2233)
  curve K62 (16.2145, -0.3272) -> (16.6934, -0.186)
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  dimension "d239" Text1-Height = 3
sketch "Sketch4" plane through (40, 0, 0) normal (1, 0, 0) x axis (0, 1, 0)
  line L1 (44.7318, 53.9359) -> (48.9918, 53.9359)
  line L2 (44.7318, 45.6759) -> (44.7318, 53.9359)
  line L3 (48.9918, 45.6759) -> (44.7318, 45.6759)
  line L4 (48.9918, 47.1259) -> (48.9918, 45.6759)
  line L5 (55.6118, 47.1259) -> (48.9918, 47.1259)
  line L6 (55.6118, 52.4859) -> (55.6118, 47.1259)
  line L7 (48.9918, 52.4859) -> (55.6118, 52.4859)
  line L8 (48.9918, 53.9359) -> (48.9918, 52.4859)
  circle C1 centre (44.7318, 49.8059) radius 0.85
  point P10 (44.7318, 49.8059)
  midpoint L2 P10
  dimension "d241" diameter C1 = 1.7 (= "filament_hole_width")
extrude "Extrude4" cut sketch "Sketch4" profile of L2 C1 no distance stored
sketch "Sketch15" plane through (-2.5, 0, 0) normal (-1, 0, 0) x axis (0, -1, 0)
  line L1 (-19.6118, 60) -> (-19.6118, 23.2332)
  line L2 (-39.6118, 60) -> (-19.6118, 60)
  line L3 (-39.6118, 52.6059) -> (-39.6118, 60)
  line L4 (-33.1118, 52.6059) -> (-39.6118, 52.6059)
  line L5 (-33.1118, 54.0559) -> (-33.1118, 52.6059)
  line L6 (-28.6118, 54.0559) -> (-33.1118, 54.0559)
  line L7 (-28.6118, 45.5559) -> (-28.6118, 54.0559)
  line L8 (-33.1118, 45.5559) -> (-28.6118, 45.5559)
  line L9 (-33.1118, 47.0059) -> (-33.1118, 45.5559)
  line L10 (-39.6118, 47.0059) -> (-33.1118, 47.0059)
  line L11 (-39.6118, 39.6118) -> (-39.6118, 47.0059)
  line L12 (-22.1725, 22.1725) -> (-39.6118, 39.6118)
  arc A1 centre (-21.1118, 23.2332) radius 1.5 clockwise from (-19.6118, 23.2332) to (-22.1725, 22.1725)
  circle C1 centre (-28.6118, 49.8059) radius 0.85
  point P16 (-28.6118, 49.8059)
  midpoint L7 P16
  dimension "d244" diameter C1 = 1.7 (= "filament_hole_width")
sketch "Sketch9" plane through (45, 0, 0) normal (1, 0, 0) x axis (0, 1, 0)
  line L1 (49.1118, 47.0059) -> (55.6118, 47.0059)
  line L2 (49.1118, 45.5559) -> (49.1118, 47.0059)
  line L3 (44.6118, 45.5559) -> (49.1118, 45.5559)
  line L4 (44.6118, 54.0559) -> (44.6118, 45.5559)
  line L5 (49.1118, 54.0559) -> (44.6118, 54.0559)
  line L6 (49.1118, 52.6059) -> (49.1118, 54.0559)
  line L7 (55.6118, 52.6059) -> (49.1118, 52.6059)
  line L8 (55.6118, 47.0059) -> (55.6118, -40)
  line L9 (39.6118, 60) -> (55.6118, 60)
  line L10 (39.6118, 52.4859) -> (39.6118, 60)
  line L11 (32.9918, 52.4859) -> (39.6118, 52.4859)
  line L12 (32.9918, 53.9359) -> (32.9918, 52.4859)
  line L13 (28.7318, 53.9359) -> (32.9918, 53.9359)
  line L14 (28.7318, 45.6759) -> (28.7318, 53.9359)
  line L15 (32.9918, 45.6759) -> (28.7318, 45.6759)
  line L16 (32.9918, 47.1259) -> (32.9918, 45.6759)
  line L17 (39.6118, 47.1259) -> (32.9918, 47.1259)
  line L18 (55.6118, 60) -> (55.6118, 52.6059)
  line L19 (39.6118, -40) -> (39.6118, 47.1259)
  line L20 (55.6118, -40) -> (39.6118, -40)
  circle C1 centre (28.7318, 49.8059) radius 0.85
  circle C2 centre (44.6118, 49.8059) radius 0.85
  point P20 (28.7318, 49.8059)
  point P21 (44.6118, 49.8059)
  midpoint L14 P20
  midpoint L4 P21
  dimension "d247" diameter C1 = 1.7 (= "filament_hole_width")
  dimension "d250" diameter C2 = 1.7 (= "filament_hole_width")
extrude "Extrude12" cut sketch "Sketch9" profile of L4 L14 C1 C2 no distance stored
sketch "Sketch16" plane through (0, 19.6118, 0) normal (0, -1, 0) x axis (1, 0, 0)
  dimension "d253" = 3
extrude "Extrude22" cut sketch "Sketch16" against normal blind 2
extrude "Extrude23" cut sketch "Sketch15" profile of L7 C1 against normal blind 260 and along normal blind 80
sketch "Sketch17" plane through (0, 19.6118, 0) normal (0, -1, 0) x axis (1, 0, 0)
  dimension "d258" = 3
extrude "Extrude24" cut sketch "Sketch17" against normal blind 2
extrude "Extrude26" cut sketch "Text" against normal blind 2
extrude "Extrude27" cut sketch "Text" against normal blind 2
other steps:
create_component "CreateComponent1"
create_component "CreateComponent2"
create_component "CreateComponent3"
create_component "CreateComponent4"
named bodies: "Wall anchor part", "Base plate with slot"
